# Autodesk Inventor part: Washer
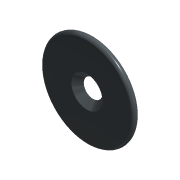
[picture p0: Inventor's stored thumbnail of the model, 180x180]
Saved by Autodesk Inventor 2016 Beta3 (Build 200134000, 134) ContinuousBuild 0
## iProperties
Created: 2016-02
Part Number: Washer
Material: Iron, Ductile
Document SubType Name: Modeling
Designer: Vertex
Density: 7.15 g/cm^3
Appearance: Iron Gray
Mass: 9.08938 g
Surface Area: 14.8469 cm^2
Volume: 1.27124 cm^3
Author: Vertex
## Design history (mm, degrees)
sketch "Sketch1"
  geometry: C1 r 15 at (0, 0); 1 further point
  constraints: 1 centre point, 1 coincident
  dimensions: "d0" = 30 diameter of C1
extrude "Extrusion1" new body sketch "Sketch1" distance "d1" = 2; taper "d2" = 0 deg
hole "Hole1" diameter "d5" = 4.13; stored, may be unused: countersink angle "d9" = 90 deg, drill point angle "d11" = 118 deg; dims "d3" = 10, "d4" = 10, "d6" = 10, "d7" = 10, "d8" = 2.5, "d10" = 14.2
fillet "Fillet1" dims "d12" = 1
body "Solid1"
